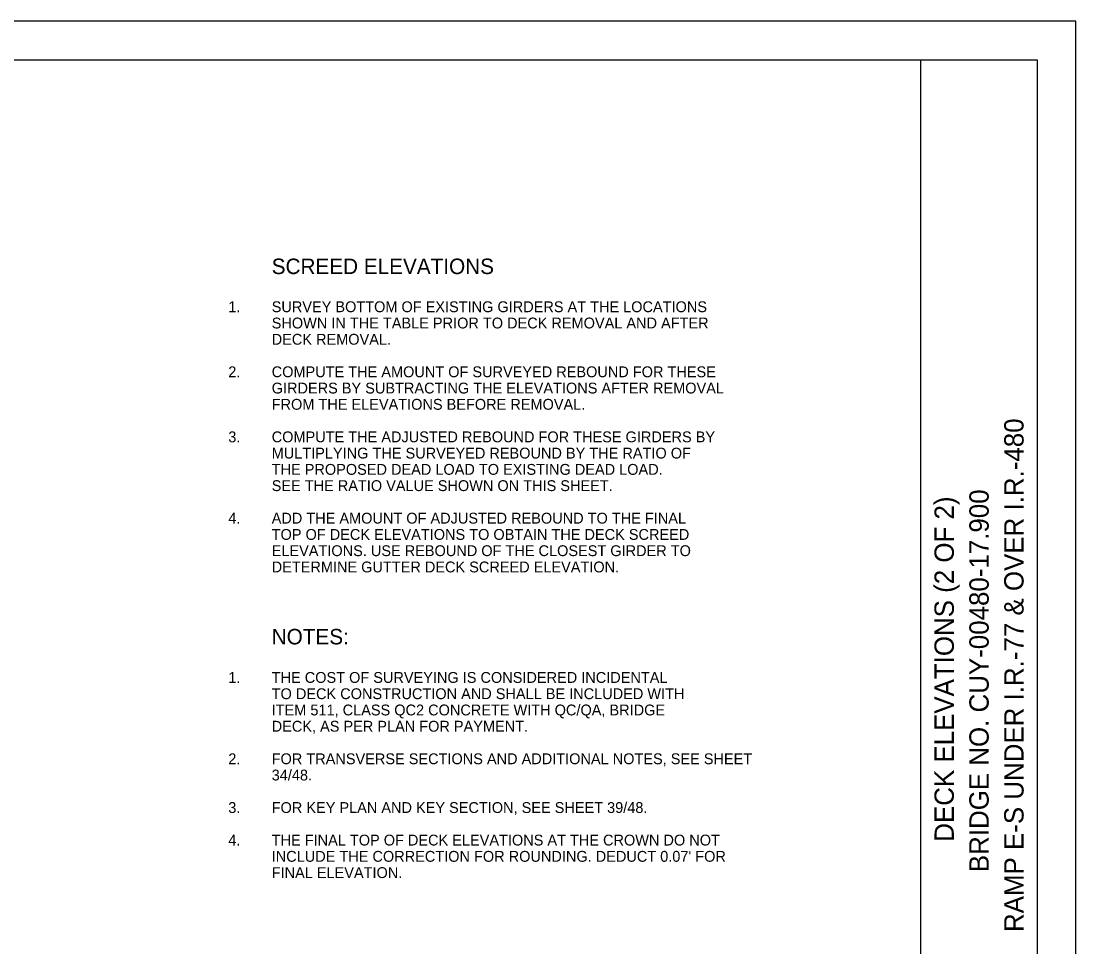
# Model space of a CAD drawing. Extents: x 0 to 34, y 0 to 22.
# Drawn here: x 20.39 to 34, y 10.04 to 22 of the extents above; entities that cross this region are included whole.
import ezdxf

# ---------------------------------------------------------------- set-up
doc = ezdxf.new("R2010")
doc.units = 0
for name, color, linetype in [('BR_P_Gen_Text', 7, 'Continuous'), ('SH_Border', 7, 'Continuous'), ('SH_Cut_Line', 7, 'Continuous'), ('SH_Data', 7, 'Continuous')]:
    doc.layers.add(name, color=color, linetype=linetype)

msp = doc.modelspace()

# ---------------------------------------------------------------- linework, layer by layer
at = {"layer": 'SH_Border'}
msp.add_line((32, 0.5), (32, 21.5), dxfattribs=at)
msp.add_lwpolyline([(1.5, 21.5), (33.5, 21.5), (33.5, 0.5), (1.5, 0.5)], close=True, dxfattribs=at)
at = {"layer": 'SH_Cut_Line'}
msp.add_lwpolyline([(0, 0), (34, 0), (34, 22), (0, 22)], close=True, dxfattribs=at)

# ---------------------------------------------------------------- texts
at = {"layer": 'BR_P_Gen_Text'}
for s, height, p in [('SCREED ELEVATIONS', 0.2, (23.623, 18.733)), ('1.   ', 0.14, (23.063, 18.241)), ('SURVEY BOTTOM OF EXISTING GIRDERS AT THE LOCATIONS ', 0.14, (23.623, 18.241)), ('SHOWN IN THE TABLE PRIOR TO DECK REMOVAL AND AFTER ', 0.14, (23.623, 18.031)), ('DECK REMOVAL.', 0.14, (23.623, 17.821)), ('2.   ', 0.14, (23.063, 17.401)), ('COMPUTE THE AMOUNT OF SURVEYED REBOUND FOR THESE', 0.14, (23.623, 17.401)), ('GIRDERS BY SUBTRACTING THE ELEVATIONS AFTER REMOVAL', 0.14, (23.623, 17.191)), ('FROM THE ELEVATIONS BEFORE REMOVAL.', 0.14, (23.623, 16.981)), ('3.   ', 0.14, (23.063, 16.561)), ('COMPUTE THE ADJUSTED REBOUND FOR THESE GIRDERS BY', 0.14, (23.623, 16.561)), ('MULTIPLYING THE SURVEYED REBOUND BY THE RATIO OF', 0.14, (23.623, 16.351)), ('THE PROPOSED DEAD LOAD TO EXISTING DEAD LOAD.', 0.14, (23.623, 16.141)), ('SEE THE RATIO VALUE SHOWN ON THIS SHEET.', 0.14, (23.623, 15.931)), ('ADD THE AMOUNT OF ADJUSTED REBOUND TO THE FINAL', 0.14, (23.623, 15.511)), ('4.   ', 0.14, (23.063, 15.511)), ('TOP OF DECK ELEVATIONS TO OBTAIN THE DECK SCREED', 0.14, (23.623, 15.301)), ('ELEVATIONS. USE REBOUND OF THE CLOSEST GIRDER TO', 0.14, (23.623, 15.091)), ('DETERMINE GUTTER DECK SCREED ELEVATION.', 0.14, (23.623, 14.881)), ('NOTES:', 0.2, (23.623, 13.951)), ('1.', 0.14, (23.063, 13.454)), ('THE COST OF SURVEYING IS CONSIDERED INCIDENTAL', 0.14, (23.623, 13.454)), ('TO DECK CONSTRUCTION AND SHALL BE INCLUDED WITH', 0.14, (23.623, 13.244)), ('ITEM 511, CLASS QC2 CONCRETE WITH QC/QA, BRIDGE', 0.14, (23.623, 13.034)), ('DECK, AS PER PLAN FOR PAYMENT.', 0.14, (23.623, 12.824)), ('2.   ', 0.14, (23.063, 12.404)), ('FOR TRANSVERSE SECTIONS AND ADDITIONAL NOTES, SEE SHEET', 0.14, (23.623, 12.404)), ('34/48.', 0.14, (23.623, 12.194)), ('3.', 0.14, (23.063, 11.774)), ('FOR KEY PLAN AND KEY SECTION, SEE SHEET 39/48.', 0.14, (23.623, 11.774)), ('4.', 0.14, (23.063, 11.354)), ('THE FINAL TOP OF DECK ELEVATIONS AT THE CROWN DO NOT', 0.14, (23.623, 11.354)), ("INCLUDE THE CORRECTION FOR ROUNDING. DEDUCT 0.07' FOR", 0.14, (23.623, 11.144)), ('FINAL ELEVATION.', 0.14, (23.623, 10.934))]:
    msp.add_text(s, height=height, dxfattribs=at).set_placement(p)
at = {"layer": 'SH_Data'}
for s, p in [('RAMP E-S UNDER I.R.-77 & OVER I.R.-480', (33.325, 10.237)), ('BRIDGE NO. CUY-00480-17.900', (32.875, 11.01)), ('DECK ELEVATIONS (2 OF 2)', (32.425, 11.403))]:
    msp.add_text(s, height=0.25, rotation=90, dxfattribs=at).set_placement(p)

doc.saveas('drawing.dxf')
